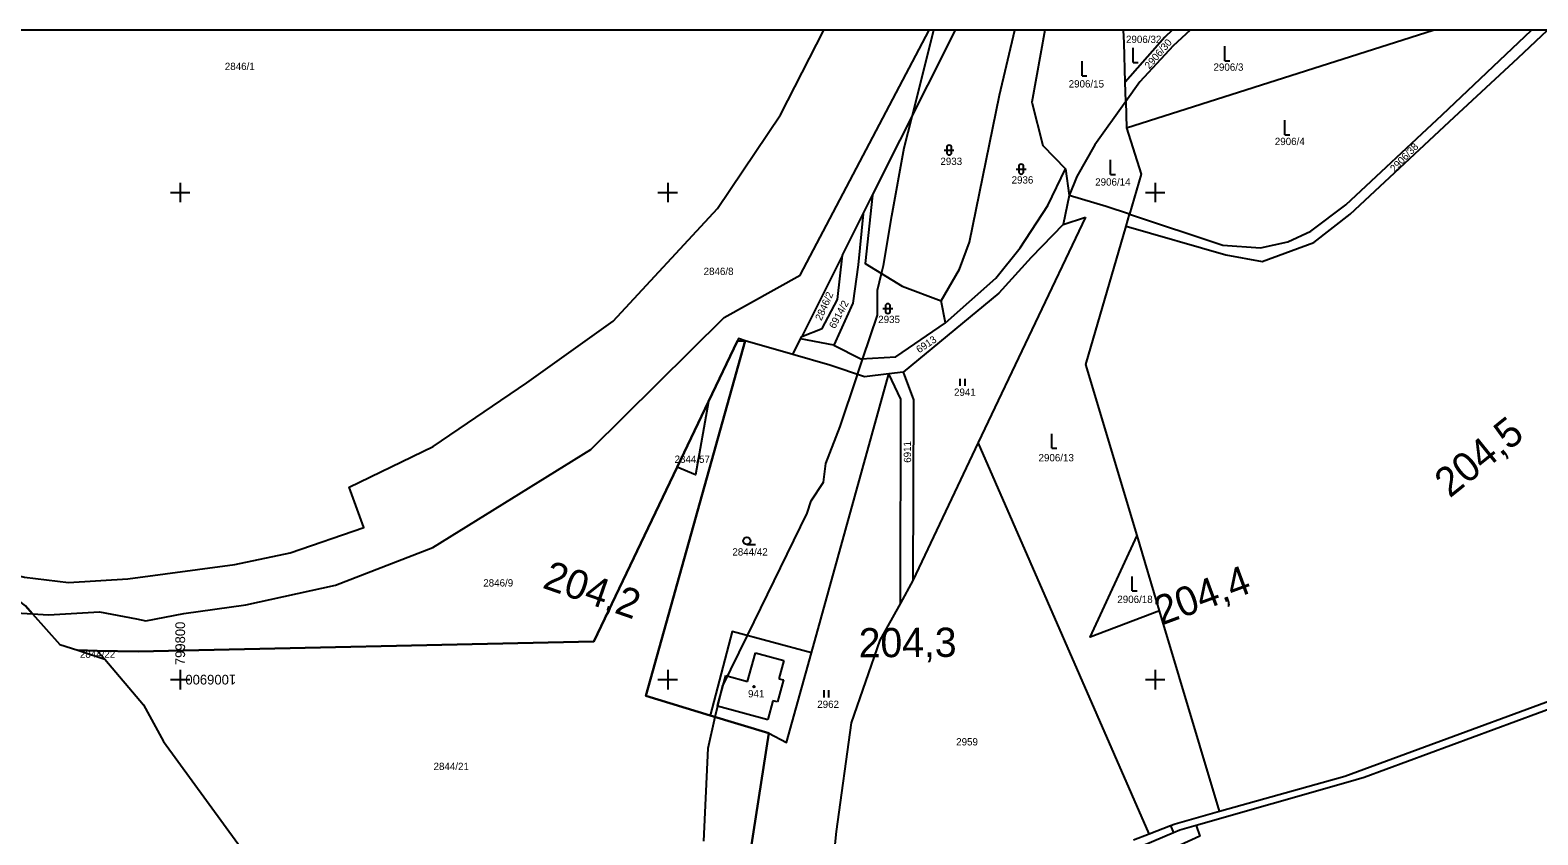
# Model space of a CAD drawing. Extents: x -800194 to -799297, y -1007177 to -1006761.
# Drawn here: x -799830.8 to -799521.5, y -1006931.9 to -1006766.6 of the extents above; entities that cross this region are included whole.
import ezdxf

# ---------------------------------------------------------------- set-up
doc = ezdxf.new("R2010")
doc.units = 0
for name, color, linetype in [('_Vrstva 7 - Přesunutá', 7, 'Continuous'), ('BPEJ', 7, 'Continuous'), ('Legenda 1', 7, 'Continuous'), ('Ramove udaje', 7, 'Continuous'), ('Vrstva 53', 7, 'Continuous'), ('Vrstva 55', 7, 'Continuous'), ('Vrstva 56', 7, 'Continuous'), ('Vrstva 57', 7, 'Continuous'), ('Vrstva 58', 7, 'Continuous'), ('Vrstva 59', 7, 'Continuous')]:
    doc.layers.add(name, color=color, linetype=linetype)

msp = doc.modelspace()

# ---------------------------------------------------------------- linework, layer by layer
at = {"layer": 'BPEJ'}
msp.add_lwpolyline([(-799692.58, -1006933.17), (-799691.73, -1006914.1), (-799690.23, -1006907.66), (-799688.77, -1006901.39), (-799683.66, -1006890.94), (-799671.4, -1006865.81), (-799670.55, -1006863.27), (-799668.01, -1006859.45), (-799667.58, -1006855.64), (-799664.62, -1006848.01), (-799661.23, -1006837.85), (-799661.07, -1006837.36), (-799659.98, -1006834.09), (-799656.99, -1006825.14), (-799656.99, -1006820.05), (-799656.13, -1006816.62), (-799655.72, -1006814.97), (-799654.03, -1006804.8), (-799651.48, -1006790.82), (-799649.85, -1006784.36), (-799645.38, -1006766.65)], dxfattribs=at)
at = {"layer": 'Legenda 1'}
msp.add_lwpolyline([(-800193.4, -1007176.65), (-799312.4, -1007176.65), (-799312.4, -1006766.65), (-800193.4, -1006766.65)], close=True, dxfattribs=at)
at = {"layer": 'Ramove udaje'}
for p, q in [((-799800, -1006798), (-799800, -1006802)), ((-799700, -1006798), (-799700, -1006802)), ((-799600, -1006798), (-799600, -1006802)), ((-799802, -1006800), (-799800, -1006800)), ((-799800, -1006800), (-799798, -1006800)), ((-799702, -1006800), (-799700, -1006800)), ((-799700, -1006800), (-799698, -1006800)), ((-799602, -1006800), (-799600, -1006800)), ((-799600, -1006800), (-799598, -1006800)), ((-799800, -1006898), (-799800, -1006902)), ((-799700, -1006898), (-799700, -1006902)), ((-799600, -1006898), (-799600, -1006902)), ((-799802, -1006900), (-799800, -1006900)), ((-799800, -1006900), (-799798, -1006900)), ((-799702, -1006900), (-799700, -1006900)), ((-799700, -1006900), (-799698, -1006900)), ((-799602, -1006900), (-799600, -1006900)), ((-799600, -1006900), (-799598, -1006900))]:
    msp.add_line(p, q, dxfattribs=at)
at = {"layer": 'Vrstva 53'}
msp.add_lwpolyline([(-799831.75, -1006884.86), (-799830.3, -1006886.5), (-799824.73, -1006892.78), (-799821.02, -1006893.98), (-799817.05, -1006894.06), (-799808.6, -1006894.22), (-799715.17, -1006892.15), (-799698.08, -1006856.38), (-799691.64, -1006842.91), (-799685.69, -1006830.46), (-799684.1, -1006830.47), (-799704.46, -1006903.31), (-799691.31, -1006907.33), (-799679.26, -1006911.01), (-799685.71, -1006952.41), (-799686.25, -1006963.73), (-799670.17, -1006962.64), (-799668.03, -1006961.74), (-799668, -1006962.02), (-799667.43, -1006981.06), (-799637.16, -1006982.06), (-799603.07, -1006978.39), (-799559.64, -1006968.48), (-799519.68, -1006952.01)], dxfattribs=at)
at = {"layer": 'Vrstva 55'}
for p, q in [((-799657.97, -1006800.56), (-799640.98, -1006766.65)), ((-799605.86, -1006786.69), (-799542.97, -1006766.65)), ((-799606.01, -1006781.28), (-799606.12, -1006777.32)), ((-799606.01, -1006781.28), (-799612.39, -1006790.22)), ((-799606.01, -1006781.28), (-799605.86, -1006786.69)), ((-799618.4, -1006795.15), (-799617.67, -1006800.63)), ((-799659.88, -1006804.37), (-799657.97, -1006800.56)), ((-799617.67, -1006800.63), (-799618.84, -1006806.56)), ((-799610.07, -1006802.89), (-799617.67, -1006800.63)), ((-799605.25, -1006804.42), (-799610.07, -1006802.89)), ((-799664.11, -1006812.82), (-799659.88, -1006804.37)), ((-799614.27, -1006805.04), (-799636.28, -1006851.33)), ((-799618.84, -1006806.56), (-799614.27, -1006805.04)), ((-799605.96, -1006806.87), (-799605.25, -1006804.42)), ((-799664.11, -1006812.82), (-799672.49, -1006829.54)), ((-799643, -1006826.73), (-799643.92, -1006822.23)), ((-799685.69, -1006830.46), (-799691.64, -1006842.91)), ((-799674.35, -1006833.26), (-799684.1, -1006830.47)), ((-799674.35, -1006833.26), (-799672.74, -1006830.04)), ((-799672.74, -1006830.04), (-799672.49, -1006829.54)), ((-799665.89, -1006831.36), (-799672.74, -1006830.04)), ((-799651.68, -1006836.84), (-799654.65, -1006837.22)), ((-799670.51, -1006894.51), (-799654.65, -1006837.22)), ((-799691.64, -1006842.91), (-799698.08, -1006856.38)), ((-799636.28, -1006851.33), (-799649.74, -1006879.63)), ((-799601.26, -1006931.67), (-799636.28, -1006851.33)), ((-799698.08, -1006856.38), (-799715.17, -1006892.15)), ((-799599.08, -1006885.89), (-799603.7, -1006870.39)), ((-799649.74, -1006879.63), (-799652.26, -1006884.27)), ((-799586.79, -1006927.02), (-799599.08, -1006885.89)), ((-799817.05, -1006894.06), (-799821.02, -1006893.98)), ((-799821.02, -1006893.98), (-799815.49, -1006895.78)), ((-799817.05, -1006894.06), (-799815.49, -1006895.78)), ((-799679.26, -1006911.01), (-799691.31, -1006907.33)), ((-799596.27, -1006931.47), (-799668.03, -1006961.74)), ((-799604.43, -1006932.91), (-799601.26, -1006931.67)), ((-799601.26, -1006931.67), (-799596.88, -1006929.97)), ((-799596.88, -1006929.97), (-799596.27, -1006931.47)), ((-799594.91, -1006930.9), (-799596.27, -1006931.47)), ((-799591.61, -1006929.95), (-799594.91, -1006930.9))]:
    msp.add_line(p, q, dxfattribs=at)
for points in [[(-799843.37, -1006876), (-799831.92, -1006878.98), (-799822.92, -1006880.05), (-799810.74, -1006879.32), (-799788.82, -1006876.36), (-799777.45, -1006873.96), (-799762.31, -1006868.73), (-799765.35, -1006860.47), (-799748.13, -1006852.13), (-799728.87, -1006839.09), (-799711.19, -1006826.38), (-799689.75, -1006803.29), (-799676.83, -1006784.06), (-799667.97, -1006766.65)], [(-799830.3, -1006886.5), (-799827.05, -1006886.7), (-799816.55, -1006886.06), (-799808.97, -1006887.52), (-799807.07, -1006887.91), (-799799.23, -1006886.45), (-799786.57, -1006884.64), (-799768.13, -1006880.63), (-799748.15, -1006872.9), (-799715.76, -1006852.76), (-799688.4, -1006825.67), (-799672.84, -1006816.93), (-799646.34, -1006766.65)], [(-799643.92, -1006822.23), (-799640.14, -1006815.75), (-799638.06, -1006810.17), (-799631.94, -1006780), (-799628.82, -1006766.65)], [(-799622.6, -1006766.65), (-799625.3, -1006781.44), (-799623.03, -1006790.37), (-799618.4, -1006795.15)], [(-799606.12, -1006777.32), (-799606.33, -1006769.27), (-799606.52, -1006766.65)], [(-799596.5, -1006766.65), (-799598, -1006768.07), (-799606.12, -1006777.32)], [(-799592.83, -1006766.65), (-799596.32, -1006769.88), (-799603.13, -1006777.25), (-799606.01, -1006781.28)], [(-799605.96, -1006806.87), (-799585.51, -1006812.81), (-799578.02, -1006814.17), (-799567.46, -1006810.26), (-799560.01, -1006804.4), (-799538.65, -1006784.55), (-799525.56, -1006772.33), (-799519.54, -1006766.65)], [(-799605.25, -1006804.42), (-799586.13, -1006810.77), (-799578.39, -1006811.38), (-799572.8, -1006810.09), (-799568.08, -1006807.93), (-799560.91, -1006802.54), (-799541.14, -1006784.06), (-799522.78, -1006766.65)], [(-799605.86, -1006786.69), (-799602.89, -1006796.25), (-799605.25, -1006804.42)], [(-799612.39, -1006790.22), (-799616.05, -1006796.73), (-799617.67, -1006800.63)], [(-799643, -1006826.73), (-799632.68, -1006817.6), (-799627.72, -1006811.33), (-799622.02, -1006802.64), (-799618.4, -1006795.15)], [(-799657.97, -1006800.56), (-799659.48, -1006814.54), (-799651.93, -1006819.24), (-799643.92, -1006822.23)], [(-799659.88, -1006804.37), (-799660.95, -1006814.84), (-799662.01, -1006822.68), (-799665.89, -1006831.36)], [(-799618.84, -1006806.56), (-799625.43, -1006813.35), (-799632.06, -1006820.64), (-799651.68, -1006836.84)], [(-799603.7, -1006870.39), (-799614.19, -1006835.28), (-799605.96, -1006806.87)], [(-799672.49, -1006829.54), (-799668.34, -1006827.91), (-799665.16, -1006821.93), (-799664.11, -1006812.82)], [(-799665.89, -1006831.36), (-799660.37, -1006834.11), (-799653.21, -1006833.72), (-799643, -1006826.73)], [(-799691.31, -1006907.33), (-799704.46, -1006903.31), (-799684.1, -1006830.47)], [(-799684.1, -1006830.47), (-799685.46, -1006829.98), (-799685.69, -1006830.46)], [(-799654.65, -1006837.22), (-799659.61, -1006837.85), (-799666.73, -1006835.44), (-799674.35, -1006833.26)], [(-799651.68, -1006836.84), (-799649.56, -1006842.56), (-799649.74, -1006879.63)], [(-799930.99, -1006838.59), (-799933.07, -1006841.6), (-799914.11, -1006855.86), (-799889.24, -1006871.28), (-799857.12, -1006884.86), (-799830.3, -1006886.5)], [(-799652.26, -1006884.27), (-799652.17, -1006842.45), (-799654.65, -1006837.22)], [(-799691.64, -1006842.91), (-799694.3, -1006857.94), (-799698.08, -1006856.38)], [(-799599.08, -1006885.89), (-799613.33, -1006891.29), (-799603.7, -1006870.39)], [(-799830.3, -1006886.5), (-799831.75, -1006884.86), (-799843.37, -1006876)], [(-799652.26, -1006884.27), (-799656.47, -1006891.91), (-799662.36, -1006908.86), (-799665.44, -1006931.17), (-799668.25, -1006959.17)], [(-799830.3, -1006886.5), (-799824.73, -1006892.78), (-799821.02, -1006893.98)], [(-799715.17, -1006892.15), (-799808.6, -1006894.22), (-799817.05, -1006894.06)], [(-799670.51, -1006894.51), (-799686.74, -1006890.11), (-799691.31, -1006907.33)], [(-799679.26, -1006911.01), (-799675.61, -1006912.91), (-799670.51, -1006894.51)], [(-799815.49, -1006895.78), (-799807.53, -1006905.17), (-799803.4, -1006912.69), (-799785.23, -1006937.71)], [(-799586.79, -1006927.02), (-799561.07, -1006919.79), (-799500.17, -1006897.39), (-799498.58, -1006896.8)], [(-799506.49, -1006901.85), (-799516.91, -1006905.73), (-799517.11, -1006905.3), (-799557.12, -1006920.07)], [(-799686.25, -1006963.73), (-799685.71, -1006952.41), (-799679.26, -1006911.01)], [(-799557.12, -1006920.07), (-799560.43, -1006921.02), (-799591.61, -1006929.95)], [(-799596.88, -1006929.97), (-799595.89, -1006929.58), (-799586.79, -1006927.02)], [(-799591.61, -1006929.95), (-799590.84, -1006932.11), (-799616.41, -1006943.81), (-799620.83, -1006945.58), (-799661.1, -1006960.05), (-799668, -1006962.02)]]:
    msp.add_lwpolyline(points, dxfattribs=at)
at = {"layer": 'Vrstva 56'}
for p, q in [((-799683.63, -1006900.36), (-799682.01, -1006894.5)), ((-799682.01, -1006894.5), (-799676.18, -1006896.08)), ((-799676.18, -1006896.08), (-799677.18, -1006899.82)), ((-799689.75, -1006905.35), (-799688.1, -1006899.14)), ((-799688.1, -1006899.14), (-799683.63, -1006900.36)), ((-799676.24, -1006900.07), (-799677.44, -1006904.58)), ((-799677.18, -1006899.82), (-799676.24, -1006900.07)), ((-799678.41, -1006904.32), (-799679.43, -1006908.15)), ((-799677.44, -1006904.58), (-799678.41, -1006904.32)), ((-799689.75, -1006905.35), (-799679.43, -1006908.15))]:
    msp.add_line(p, q, dxfattribs=at)
at = {"layer": 'Vrstva 58'}
for p, q in [((-799604.51, -1006773.29), (-799604.51, -1006770.29)), ((-799585.7, -1006772.93), (-799585.7, -1006769.93)), ((-799614.99, -1006776.01), (-799614.99, -1006773.01)), ((-799604.51, -1006773.29), (-799603.51, -1006773.29)), ((-799585.7, -1006772.93), (-799584.7, -1006772.93)), ((-799614.99, -1006776.01), (-799613.99, -1006776.01)), ((-799573.38, -1006788.16), (-799573.38, -1006785.16)), ((-799573.38, -1006788.16), (-799572.38, -1006788.16)), ((-799643.27, -1006791.27), (-799641.27, -1006791.27)), ((-799642.77, -1006790.77), (-799642.77, -1006791.77)), ((-799641.77, -1006791.77), (-799641.77, -1006790.77)), ((-799609.15, -1006796.29), (-799609.15, -1006793.29)), ((-799628.48, -1006795.19), (-799626.48, -1006795.19)), ((-799627.98, -1006794.69), (-799627.98, -1006795.69)), ((-799626.98, -1006795.69), (-799626.98, -1006794.69)), ((-799609.15, -1006796.29), (-799608.15, -1006796.29)), ((-799655.84, -1006823.82), (-799653.84, -1006823.82)), ((-799655.34, -1006823.32), (-799655.34, -1006824.32)), ((-799654.34, -1006824.32), (-799654.34, -1006823.32)), ((-799639.98, -1006839.71), (-799639.98, -1006838.21)), ((-799638.98, -1006839.71), (-799638.98, -1006838.21)), ((-799621.18, -1006852.51), (-799621.18, -1006849.51)), ((-799621.18, -1006852.51), (-799620.18, -1006852.51)), ((-799683.77, -1006872.27), (-799682.02, -1006872.27)), ((-799604.71, -1006881.8), (-799604.71, -1006878.8)), ((-799604.71, -1006881.8), (-799603.71, -1006881.8)), ((-799667.92, -1006903.67), (-799667.92, -1006902.17)), ((-799666.92, -1006903.67), (-799666.92, -1006902.17))]:
    msp.add_line(p, q, dxfattribs=at)
msp.add_circle((-799683.77, -1006871.52), 0.75, dxfattribs=at)
for centre, start, end in [((-799642.27, -1006790.77), 0, 180), ((-799642.27, -1006791.77), 180, 359.9879), ((-799627.48, -1006794.69), 0, 180), ((-799627.48, -1006795.69), 180, 359.9879), ((-799654.84, -1006823.32), 0, 180), ((-799654.84, -1006824.32), 180, 359.9879)]:
    msp.add_arc(centre, 0.5, start, end, dxfattribs=at)
at = {"layer": 'Vrstva 59'}
msp.add_circle((-799682.3, -1006901.44), 0.175, dxfattribs=at)

# ---------------------------------------------------------------- texts
at = {"layer": '_Vrstva 7 - Přesunutá'}
for s, rotation, p in [('204,5', 38.8758, (-799539.57, -1006862.84)), ('204,2', 340.8787, (-799725.91, -1006881.09)), ('204,4', 20.2403, (-799598.78, -1006888.95)), ('204,3', 0.3246, (-799660.8, -1006895.43))]:
    msp.add_text(s, height=6, rotation=rotation, dxfattribs=at).set_placement(p)
at = {"layer": 'Ramove udaje'}
for s, rotation, p in [('    799800', 90, (-799799, -1006900)), ('1006900    ', 180, (-799788.53, -1006899))]:
    msp.add_text(s, height=2, rotation=rotation, dxfattribs=at).set_placement(p)
at = {"layer": 'Vrstva 57'}
for s, p in [('2906/32', (-799605.98, -1006769.29)), ('2846/1', (-799790.85, -1006774.84)), ('2906/3', (-799588.03, -1006774.99)), ('2906/15', (-799617.74, -1006778.43)), ('2906/4', (-799575.45, -1006790.25)), ('2933', (-799644.06, -1006794.33)), ('2936', (-799629.45, -1006798.15)), ('2906/14', (-799612.3, -1006798.57)), ('2846/8', (-799692.63, -1006816.92)), ('2935', (-799656.81, -1006826.79)), ('2941', (-799641.26, -1006841.73)), ('2844/57', (-799698.59, -1006855.49)), ('2906/13', (-799623.92, -1006855.18)), ('2844/42', (-799686.73, -1006874.52)), ('2846/9', (-799737.83, -1006880.88)), ('2906/18', (-799607.76, -1006884.26)), ('2844/22', (-799820.58, -1006895.51)), ('941', (-799683.52, -1006903.64)), ('2962', (-799669.32, -1006905.81)), ('2959', (-799640.82, -1006913.51)), ('2844/21', (-799748.03, -1006918.56))]:
    msp.add_text(s, height=1.5, dxfattribs=at).set_placement(p)
for s, rotation, p in [('2906/30', 49.0973, (-799601.19, -1006774.75)), ('2906/38', 46, (-799550.91, -1006795.91)), ('2846/2', 66, (-799668.46, -1006826.42)), ('6914/2', 62, (-799665.68, -1006828.07)), ('6913', 34, (-799648.39, -1006833.03)), ('6911', 91, (-799650.05, -1006855.46))]:
    msp.add_text(s, height=1.5, rotation=rotation, dxfattribs=at).set_placement(p)

doc.saveas('drawing.dxf')
